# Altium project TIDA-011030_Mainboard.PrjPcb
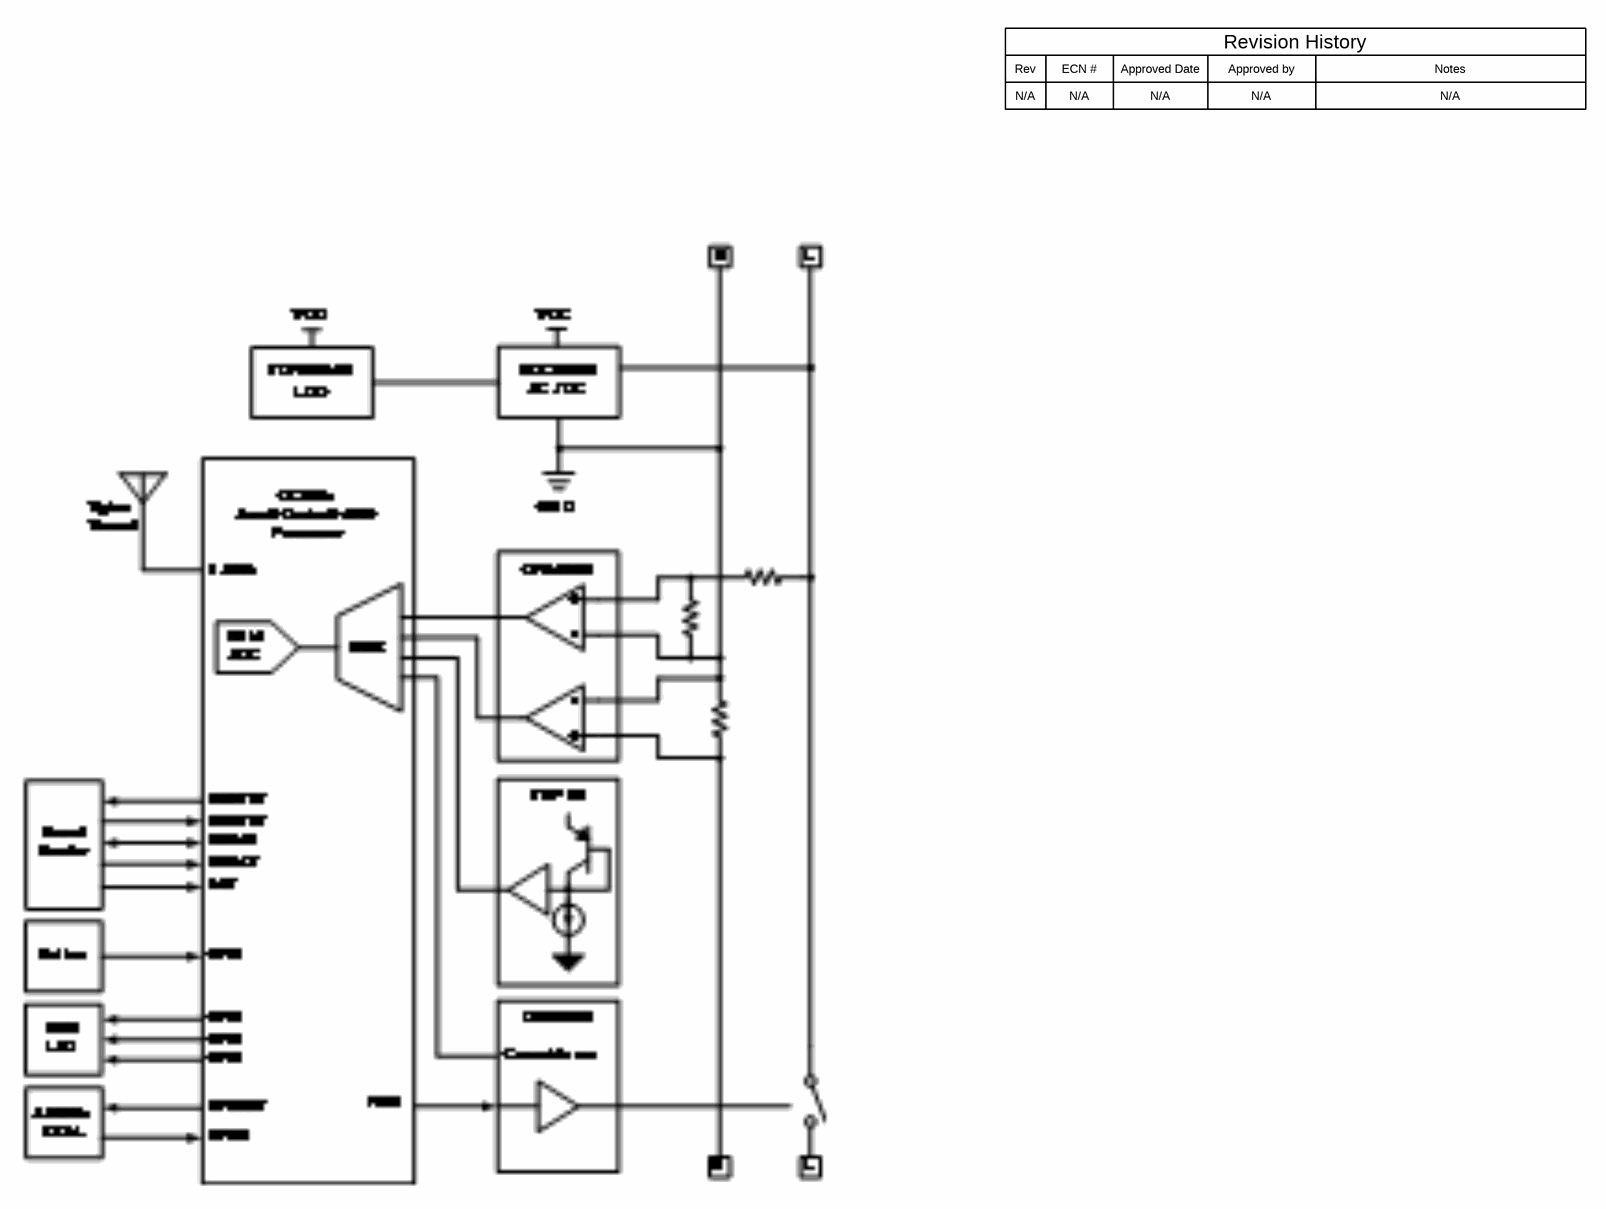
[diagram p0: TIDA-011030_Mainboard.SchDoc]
CopyrightYear: 2026; PCB_Layout: Simon Bozowicki; PCB_Rev: E1; PRJ_Customer: Public Release; PRJ_Engineer: Simon Bozowicki; PRJ_Number: TIDA-011030; PRJ_Title: Smart Circuit Breaker; SCH_Rev: E1; TechSupport: http://www.ti.com/support; TID: TIDA-011030
6 sheets, 114 parts. Net scope: flat (ports and power ports of the same name join across sheets).
Board file: TIDA-011030_Mainboard.PcbDoc
Sheets:
  TIDA-011030_Mainboard.SchDoc
  TIDA-011030_Mainboard_MCU.SchDoc
  TIDA-011030_Mainboard_Metering.SchDoc
  TIDA-011030_Mainboard_RelayDRV.SchDoc
  TIDA-011030_Mainboard_Power.SchDoc
  TIDA-011030_Mainboard_Hardware.SchDoc

## Sheet TIDA-011030_Mainboard.SchDoc: Block Diagram
size 431 x 279 mm; Date: Not shown in title block; ApprovedBy: Not shown in title block; CheckedBy: Not shown in title block; Author: Not shown in title block; CompanyName: Not shown in title block; Engineer: Not shown in title block; Organization: Not shown in title block; Address1: Not shown in title block; Address2: Not shown in title block; Address3: Not shown in title block; Address4: Not shown in title block; DocumentNumber: 1; Revision: Use project parameter SCH_Rev; SheetNumber: 1; SheetTotal: 6; PageSetup: Record=PageOptions¦CenterHorizontal=True¦CenterVertical=True¦PrintScale=1.00¦XCorrection=1.00¦YCorrection=1.00¦PrintKind=0¦BorderSize=5000000¦LeftOffset=0¦BottomOffset=0¦Orientation=2¦PaperLength=1000¦PaperWidth=1000¦Scale=100¦PaperSource=15¦PrintQuality=600¦MediaType=1¦DitherType=10¦PaperKind=Letter¦PrintScaleMode=1

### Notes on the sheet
- Rev
- N/A
- ECN #
- Approved Date
- Approved by
- Revision History
- Notes

## Sheet TIDA-011030_Mainboard_MCU.SchDoc: MCU
size 431 x 279 mm; Date: Not shown in title block; ApprovedBy: Not shown in title block; CheckedBy: Not shown in title block; Author: Not shown in title block; CompanyName: Not shown in title block; Engineer: Not shown in title block; Organization: Not shown in title block; Address1: Not shown in title block; Address2: Not shown in title block; Address3: Not shown in title block; Address4: Not shown in title block; DocumentNumber: 1; Revision: Use project parameter SCH_Rev; SheetNumber: 2; SheetTotal: 6; PageSetup: Record=PageOptions¦CenterHorizontal=True¦CenterVertical=True¦PrintScale=1.00¦XCorrection=1.00¦YCorrection=1.00¦PrintKind=0¦BorderSize=5000000¦LeftOffset=0¦BottomOffset=0¦Orientation=2¦PaperLength=1000¦PaperWidth=1000¦Scale=100¦PaperSource=15¦PrintQuality=600¦MediaType=1¦DitherType=10¦PaperKind=Letter¦PrintScaleMode=1
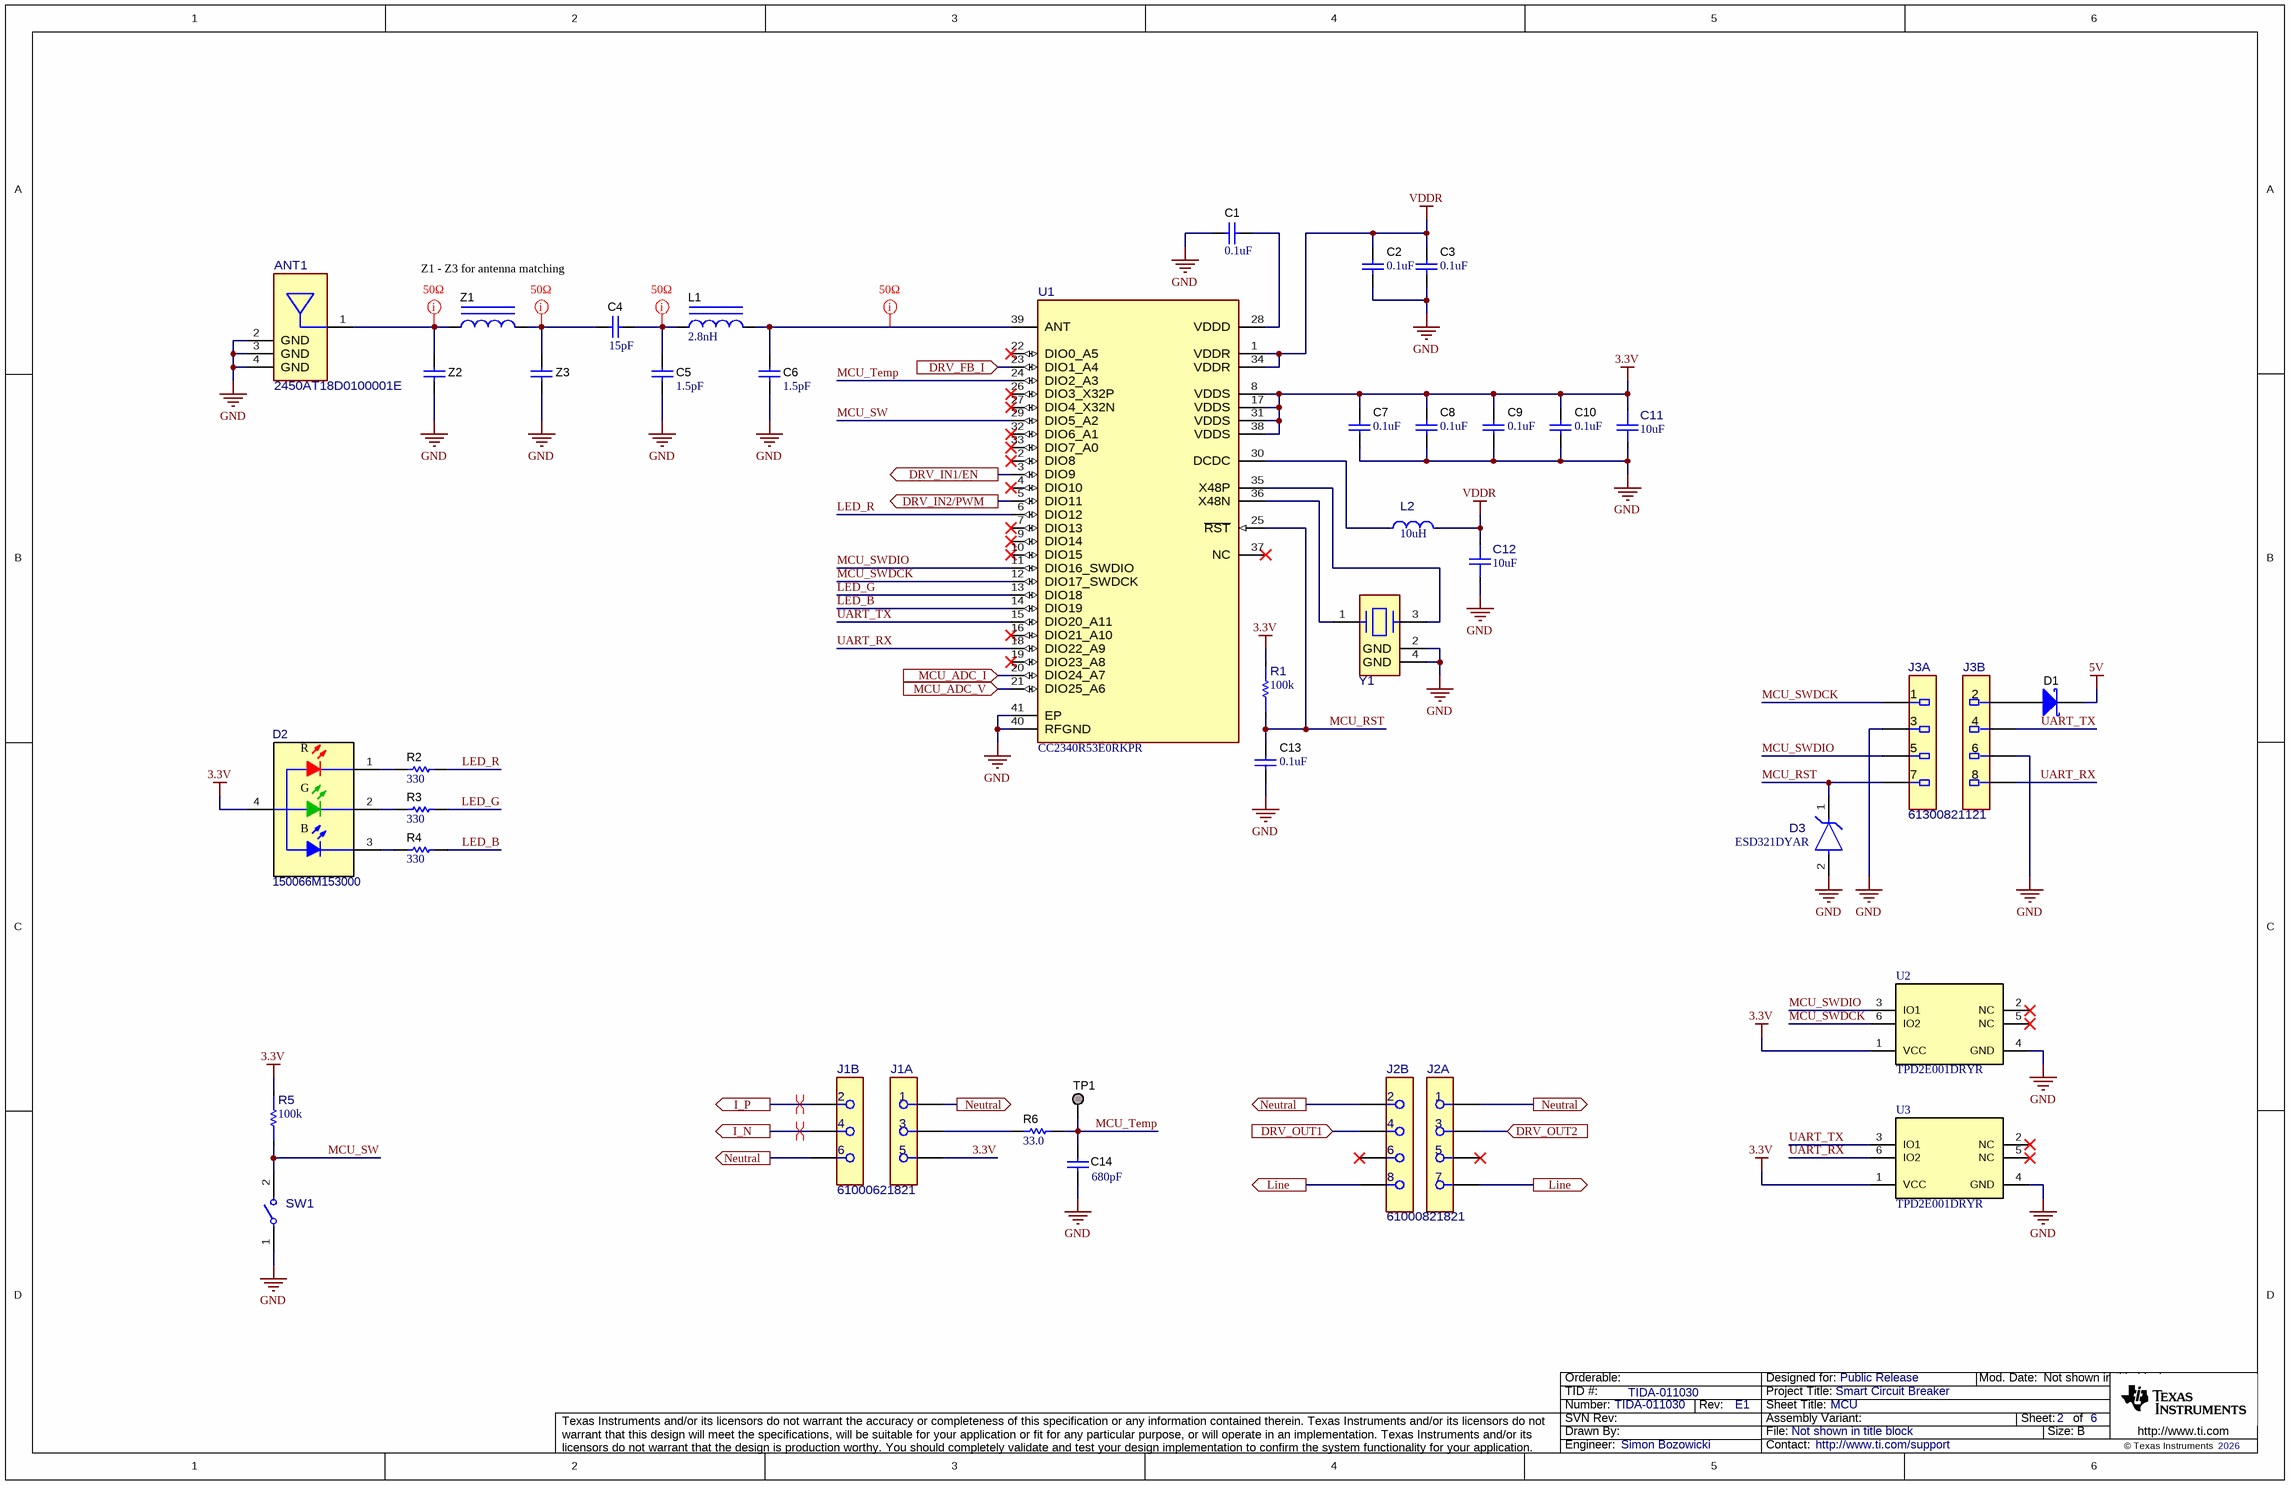
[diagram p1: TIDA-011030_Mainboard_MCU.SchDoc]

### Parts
ANT1  2450AT18D0100001E  [FP-2450AT18D0100001E_1206-MFG]
C1  ValueDisplayed: 0.1uF  [0402]  (hidden comment: GCM155R71C104KA55D)
C2  ValueDisplayed: 0.1uF  [0402]  (hidden comment: GCM155R71C104KA55D)
C3  ValueDisplayed: 0.1uF  [0402]  (hidden comment: GCM155R71C104KA55D)
C4  ValueDisplayed: 15pF  [0402]  (hidden comment: 04025A150FAT2A)
C5  ValueDisplayed: 1.5pF  [0402]  (hidden comment: GRM1555C1H1R5CA01D)
C6  ValueDisplayed: 1.5pF  [0402]  (hidden comment: GRM1555C1H1R5CA01D)
C7  ValueDisplayed: 0.1uF  [0402]  (hidden comment: GCM155R71C104KA55D)
C8  ValueDisplayed: 0.1uF  [0402]  (hidden comment: GCM155R71C104KA55D)
C9  ValueDisplayed: 0.1uF  [0402]  (hidden comment: GCM155R71C104KA55D)
C10  ValueDisplayed: 0.1uF  [0402]  (hidden comment: GCM155R71C104KA55D)
C11  ValueDisplayed: 10uF  [FP-GRT188D71A106ME13D_0603-MFG]  (hidden comment: GRT188D71A106ME13D)
C12  ValueDisplayed: 10uF  [FP-GRT188D71A106ME13D_0603-MFG]  (hidden comment: GRT188D71A106ME13D)
C13  ValueDisplayed: 0.1uF  [0402]  (hidden comment: GCM155R71C104KA55D)
C14  ValueDisplayed: 680pF  [0402]  (hidden comment: GRM155R71H681KA01D)
D1  PMEG3005ELS-QYL  [FP-PMEG3005ELS-QYL_DFN1006BD-2-0]  (value not drawn)
D2  150066M153000  [WL-SFCD0606_RGB]
D3  ESD321DYAR  [DYA0002A-MFG]
J1  61000621821  [FP-61000621821_HDR6-MFG]  (parts A,B of 2)
J2  61000821821  [FP-61000821821_CONN_RCPT_8-MFG]  (parts A,B of 2)
J3  61300821121  [FP-61300821121_HDR8-MFG]  (parts A,B of 2)
L1  ValueDisplayed: 2.8nH  [LQG15WZ_02]  (hidden comment: LQG15WZ2N8B02D)
L2  value 10uH  [FP-LQM18DH100M70L_0603-MFG]  (hidden comment: LQM18DH100M70L)
R1  value 100k  [FP-CRCW0402100KFKEDC_0402-MFG]  (hidden comment: CRCW0402100KFKEDC)
R2  ValueDisplayed: 330  [0402]  (hidden comment: ERJ-2RKF3300X)
R3  ValueDisplayed: 330  [0402]  (hidden comment: ERJ-2RKF3300X)
R4  ValueDisplayed: 330  [0402]  (hidden comment: ERJ-2RKF3300X)
R5  value 100k  [FP-CRCW0402100KFKEDC_0402-MFG]  (hidden comment: CRCW0402100KFKEDC)
R6  ValueDisplayed: 33.0  [0402]  (hidden comment: RC0402FR-0733RL)
SW1  430133050816  [FP-430133050816_SMD2-MFG]  (value not drawn)
TP1  TP_SM_1MM  [TP_SM_1MM]  (value not drawn)  (no BOM)
U1  CC2340R53E0RKPR  [RKP0040B-MFG]
U2  TPD2E001DRYR  [DRY0006A]
U3  TPD2E001DRYR  [DRY0006A]
Y1  TZ3908AAAO43  [FP-TZ3908AAAO43_SMT4_2MM05_1MM65-MFG]  (value not drawn)
Z1  LQG15WZ1N9S02D  [LQG15WZ_02]  (value not drawn)
Z2  GRM1555C1H1R5CA01D  [0402]  (value not drawn)
Z3  GRM1555C1H1R5CA01D  [0402]  (value not drawn)

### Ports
DRV_FB_I (in), DRV_IN1/EN (out), DRV_IN2/PWM (out), DRV_OUT1 (in), DRV_OUT2 (in), I_N (out), I_P (out), Line (out), MCU_ADC_I (in), MCU_ADC_V (in), Neutral (out)

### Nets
3.3V: C7.1 C8.1 C9.1 C10.1 C11.1 D2.4(A) J1.5 R1.2 R5.2 U1.8(VDDS) U1.17(VDDS) U1.31(VDDS) U1.38(VDDS) U2.1(VCC) U3.1(VCC)
5V: D1.1(K)
GND: ANT1.2(GND) ANT1.3(GND) ANT1.4(GND) C1.1 C2.2 C3.2 C5.2 C6.2 C7.2 C8.2 C9.2 C10.2 C11.2 C12.2 C13.2 C14.2 D3.2(GND) J1.1 J1.6 J2.1 J2.2 J3.3 J3.6 SW1.1 U1.40(RFGND) U1.41(EP) U2.4(GND) U3.4(GND) Y1.2(GND) Y1.4(GND) Z2.2 Z3.2 ; port Neutral
VDDR: C2.1 C3.1 C12.1 L2.2 U1.1(VDDR) U1.34(VDDR)
DRV_FB_I: U1.23(DIO1_A4) ; port DRV_FB_I
DRV_IN1/EN: U1.3(DIO9) ; port DRV_IN1/EN
DRV_IN2/PWM: U1.5(DIO11) ; port DRV_IN2/PWM
DRV_OUT1: J2.4 ; port DRV_OUT1
DRV_OUT2: J2.3 ; port DRV_OUT2
I_N: J1.4 ; port I_N
I_P: J1.2 ; port I_P
LED_B: R4.2 U1.14(DIO19)
LED_G: R3.2 U1.13(DIO18)
LED_R: R2.2 U1.6(DIO12)
Line: J2.7 J2.8 ; port Line
MCU_ADC_I: U1.20(DIO24_A7) ; port MCU_ADC_I
MCU_ADC_V: U1.21(DIO25_A6) ; port MCU_ADC_V
MCU_RST: C13.1 D3.1(IO) J3.7 R1.1 U1.25(~{RST})
MCU_SW: R5.1 SW1.2 U1.29(DIO5_A2)
MCU_SWDCK: J3.1 U1.12(DIO17_SWDCK) U2.6(IO2)
MCU_SWDIO: J3.5 U1.11(DIO16_SWDIO) U2.3(IO1)
MCU_Temp: C14.1 R6.2 TP1.1 U1.24(DIO2_A3)
UART_RX: J3.8 U1.18(DIO22_A9) U3.6(IO2)
UART_TX: J3.4 U1.15(DIO20_A11) U3.3(IO1)
NetANT1_1: ANT1.1(FEED) Z1.1 Z2.1
NetC1_2: C1.2 U1.28(VDDD)
NetC4_1: C4.1 C5.1 L1.1
NetC4_2: C4.2 Z1.2 Z3.1
NetC6_1: C6.1 L1.2 U1.39(ANT)
NetD1_2: D1.2(A) J3.2
NetD2_1: D2.1(K) R2.1
NetD2_2: D2.2(K) R3.1
NetD2_3: D2.3(K) R4.1
NetJ1_3: J1.3 R6.1
NetL2_1: L2.1 U1.30(DCDC)
NetU1_35: U1.35(X48P) Y1.3(2_IN/OUT)
NetU1_36: U1.36(X48N) Y1.1(1_IN/OUT)

Not connected (* = marked no-connect by the designer): J2 5* 6*; U1 2(DIO8)* 4(DIO10)* 7(DIO13)* 9(DIO14)* 10(DIO15)* 16(DIO21_A10)* 19(DIO23_A8)* 22(DIO0_A5)* 26(DIO3_X32P)* 27(DIO4_X32N)* 32(DIO6_A1)* 33(DIO7_A0)* 37(NC)*; U2 2(NC)* 5(NC)*; U3 2(NC)* 5(NC)*

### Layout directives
mark named 50Ω: NetANT1_1, NetC4_1, NetC4_2, NetC6_1
differential pair: I_N, I_P

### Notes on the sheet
- Z1 - Z3 for antenna matching

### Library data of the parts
ANT1 = CMP-0121196-1: 2.4GHz Chip RF Antenna 2.4GHz ~ 2.5GHz 1.5dBi Solder Surface Mount; Manufacturer: Johanson; SizeZ_mm: 1.3mm; AEC Qualified: No; Bandwidth: 0.1GHz; Gain: -1dB; Impedance: 50Ω; Number Of Bands: 1; Power_W: 3W; Return Loss: 10dB
C1-C3 C7-C10 C13 = CMP-0006351-2: CAP, CERM, 0.1 uF, 16 V, +/- 10%, X7R, 0402; Manufacturer: MuRata; TaMin_C: -55°C; Polarized: N; SizeAreaWB_mm2: 3; Value1: Unknown; U/M: EA; Value: 0.1uF; TaMax_C: 125°C; SizeZ_mm: 0.6; SizeX_mm: 1; SizeY_mm: 0.5; Value2: 16V; Cap_F: 100nF; AEC Category: Q200
C4 = CMP-0078217-1: CAP, CERM, 15 pF, 50 V,+/- 1%, C0G/NP0, 0402; Manufacturer: AVX; TaMin_C: -55°C; Polarized: N; Green_Lifecycle: Not Set; SizeAreaWB_mm2: 3; Green_REACh: Incomplete; U/M: EA; Value: 15pF; TaMax_C: 125°C; SizeZ_mm: 0.6; SizeX_mm: 1; SizeY_mm: 0.5; Value2: 50V; AEC Category: Q200
C5 C6 Z2 Z3 = CMP-0006433-2: CAP, CERM, 1.5 pF, 50 V, +/- 5%, C0G/NP0, 0402; Manufacturer: MuRata; TaMin_C: -55°C; Polarized: N; SizeAreaWB_mm2: 3; Value1: Unknown; U/M: EA; Value: 1.5pF; TaMax_C: 125°C; SizeZ_mm: 0.6; SizeX_mm: 1; SizeY_mm: 0.5; Value2: 50V; AEC Category: Q200
C11 C12 = CMP-0124993-1: Multi-Layer Ceramic Capacitor 10uF 10V X7T ±20% 0603 Paper T/R; Manufacturer: Murata; AEC Grade: Grade 1; AEC Qualified: Yes; Cap_F: 10µF; SizeZ_mm: 1mm; TempCo: +22/-33%; Value: 10µF
C14 = CMP-0006695-2: CAP, CERM, 680 pF, 50 V, +/- 10%, X7R, 0402; Manufacturer: MuRata; TaMin_C: -55°C; Polarized: N; SizeAreaWB_mm2: 3; Value1: Unknown; U/M: EA; Value: 680pF; TaMax_C: 125°C; SizeZ_mm: 0.6; SizeX_mm: 1; SizeY_mm: 0.5; Value2: 50V; AEC Category: Q200
D1 = CMP-0123792-2: Diode 30 V 500mA Surface Mount DFN1006BD-2; Manufacturer: Nexperia; AEC Qualified: Yes; SizeZ_mm: 0.5mm; TJmax_C: 150°C; Vr_V: 30V; AEC Grade: Grade 0; Cap_F: 24pF; Forward Current: 0.5A; Max Surge Forward Current: 3A; Peak Reverse Current: 70uA; TaMax_C: +150°C; TaMin_C: -55°C; AEC Category: Q101
D2 = CMP-0067667-2: LED, RGB, SMD; Manufacturer: Wurth Elektronik; Angle: 120.0; Io_A: 20mA; Value1: 0.078W; Vf_V: 3.3V; SizeZ_mm: 0.5; Tjmax_C: 85°C; SizeY_mm: 1.6; Power_TotalModule: 78mW; SizeAreaWB_mm2: 6.76; SizeArea_mm2: 2.56; Ir_A: 100µA; Type: InGaN; Vr_V: 5V
D3 = CMP-0125991-1: 0.9pF 3.6V ±30kV ESD protection diode with 6.8V 16A TLP clamping for USB 2.0 2-SOT-5X3 -55 to 150; Manufacturer: Texas Instruments; AEC Qualified: No; SizeZ_mm: 0.77mm; Ipp: 6A; Ppk: 40W; Breakdown Voltage: 4.5V; Clamping Voltage: 6.3V; Direction: Unidirectional; Number Of Channels: 1; Standoff Height: 0mm; TaMax_C: +125°C; TaMin_C: -40°C
J1 = CMP-0128753-1: WR-PHD 2.54 mm Dual Row SMT Socket Header 6 pins; Manufacturer: Wurth Electronics; ContactFinish: Gold; Current_A: 3A; Row_Count: 2; Voltage_V: 250V; AEC Qualified: No; Conn Gender: Female; Conn Orientation: Straight; DUT-Pitch_mm: 2.54mm; Is Female: yes; SizeZ_mm: 7.6mm; System: Connector
J2 = CMP-0128754-1: CONNECTOR, RCPT, 8POS, 2ROW, 2.54MM; Manufacturer: Wurth Electronics; ContactFinish: Gold; Current_A: 3A; Row_Count: 2; Voltage_V: 250V; AEC Qualified: No; Conn Gender: Female; Conn Orientation: Straight; Is Female: yes; SizeZ_mm: 7.6mm
J3 = CMP-0087153-1: CONN HEADER VERT 8POS 2.54MM; Manufacturer: Wurth Electronics; Voltage_V: 250V; Row_Count: 2; Current_A: 3A; ContactFinish: Gold
L1 = CMP-0080227-3: Inductor, Multilayer, Air Core, 2.8 nH, 0.9 A, 0.08 ohm, AEC-Q200 Grade 1, SMD; Manufacturer: MuRata; Irms: 0.9A @ 25C rise; SizeAreaWB_mm2: 3.2; DCR_ohm: 0.08; Value: 2.8nH; Imax_A: 900mA; SizeZ_mm: 0.6; SizeX_mm: 1; Value2: 0.9A; AEC Qualified: Y; AEC Category: Q200
L2 = CMP-0050143-1: 10 µH Shielded Multilayer Inductor 300 mA 1.37Ohm Max 0603 (1608 Metric); Manufacturer: Murata; AEC Grade: Grade 0; AEC Qualified: Yes; DCR_ohm: 1.37; Ind_H: 10µH; Irms: 300mA; Isat: 100mA; Material: Ferrite; SizeZ_mm: 0.95mm; Self Resonant Frequency: 32MHz; Shrouded: true; Test Frequency: 1MHz; Tolerance_%: 20%
R1 R5 = CMP-0092204-1: 100 kOhms ±1% 0.063W, 1/16W Chip Resistor 0402 (1005 Metric)  Thick Film; Manufacturer: Vishay; Power_W: 63mW; AEC Qualified: No; TempCo: 100ppm/°C; SizeZ_mm: 0.35mm; VDC_V: 50V
R2-R4 = CMP-0026694-1: RES, 330, 1%, 0.1 W, AEC-Q200 Grade 0, 0402; Manufacturer: Panasonic; Power_W: 100mW; TempCo: 100 ppm/C; Value_Code: 330R; U/M: EA; Value: 330; SizeX_mm: 1; SizeY_mm: 0.5; SizeZ_mm: 0.6; Value2: 0.1W; AEC Qualified: Y; VDC_V: 50V; AEC Grade: 0; AEC Category: Q200
R6 = CMP-0026732-1: RES, 33.0, 1%, 0.062 W, 0402; Manufacturer: Yageo America; Power_W: 62mW; TempCo: 100 ppm/C; Value_Code: 33R0; U/M: EA; Value: 33.0; Res_ohm: 33; SizeX_mm: 1; SizeY_mm: 0.5; SizeZ_mm: 0.6; Value2: 0.062W; AEC Qualified: N; VDC_V: 50V; AEC Category: Q200
SW1 = CMP-0128770-1: Tactile Switch SPST-NO Top Actuated Surface Mount; Manufacturer: Wurth; SizeZ_mm: 5.2mm; VDC_V: 16V; AEC Qualified: No; Coil Resistance_ohm: 100mΩ; Contact Current Rating: 50mA; Electromechanical Life: 100000Cycles; Operating Force: 160gf
TP1 = CMP-0003825-1: 1mm Test Point, SMT; Manufacturer: Any
U1 = CMP-0121694-1: SimpleLink™ Bluetooth ® 5.3 Low Energy Wireless MCU, VQFN40; Manufacturer: Texas Instruments; SizeZ_mm: 1mm; AEC Qualified: No; AEC Grade: NA; Core Architecture: ARM Cortex-M0+; Data Bus Width: 32bits; Frequency_Fixed: 48MHz; Interface: I2C,SPI,UART; Max Supply Voltage: 3.8V; Memory Size: 512KBytes; Memory Type: FLASH; Min Supply Voltage: 1.71V; Number Of A/D Converters: 1; Number Of Adc Channels: 8; Number Of I/Os: 26; Number Of Timers/Counters: 4; Ram Size: 36KBytes; Standoff Height: 0mm; TaMax_C: +125°C; TaMin_C: -40°C
U2 U3 = CMP-0043099-3: Low-Capacitance 2-Channel +/-15kV ESD Protection Array for High-Speed Data Interfaces, DRY0006A (USON-6); Manufacturer: Texas Instruments; IO Leakage Current(nA): 1; IEC 61000-4-2 Air-Gap(+/- kV): 15; USB High Speed: TRUE; IO Capacitance(Typ)(pF): 1.5; Eco-Plan: Green (RoHS & no Sb/Br); Breakdown Voltage(Min)(V): 11; IEC 61000-4-2 Contact(+/- kV): 8; AEC Category: Q200; AEC Qualified: N; CompType: IC; SizeAreaWB_mm2: 4.9; SizeArea_mm2: 1.45; SizeX_mm: 1.0; SizeZ_mm: 0.6; Rating: Catalog
Y1 = CMP-0001392-1: Crystal Unit SMD 2.0x1.6 48.0MHz; Manufacturer: TAI-SAW Thechnology; Frequency Stability: 30ppm; Frequency_Fixed: 48MHz; SizeZ_mm: 0.5mm; AEC Qualified: No; Frequency Tolerance: 5ppm; Load Capacitance: 7pF; Esr: 30
Z1 = CMP-0080187-3: Inductor, Multilayer, Air Core, 1.9 nH, 1 A, 0.05 ohm, AEC-Q200 Grade 1, SMD; Manufacturer: MuRata; Irms: 1A @ 25C rise; SizeAreaWB_mm2: 3.2; DCR_ohm: 0.05; Value: 1.9nH; Imax_A: 1A; SizeZ_mm: 0.6; SizeX_mm: 1; AEC Qualified: Y; AEC Category: Q200

## Sheet TIDA-011030_Mainboard_Metering.SchDoc: Metering
size 431 x 279 mm; Date: Not shown in title block; ApprovedBy: Not shown in title block; CheckedBy: Not shown in title block; Author: Not shown in title block; CompanyName: Not shown in title block; Engineer: Not shown in title block; Organization: Not shown in title block; Address1: Not shown in title block; Address2: Not shown in title block; Address3: Not shown in title block; Address4: Not shown in title block; DocumentNumber: 1; Revision: Use project parameter SCH_Rev; SheetNumber: 3; SheetTotal: 6; PageSetup: Record=PageOptions¦CenterHorizontal=True¦CenterVertical=True¦PrintScale=1.00¦XCorrection=1.00¦YCorrection=1.00¦PrintKind=0¦BorderSize=5000000¦LeftOffset=0¦BottomOffset=0¦Orientation=2¦PaperLength=1000¦PaperWidth=1000¦Scale=100¦PaperSource=15¦PrintQuality=600¦MediaType=1¦DitherType=10¦PaperKind=Letter¦PrintScaleMode=1
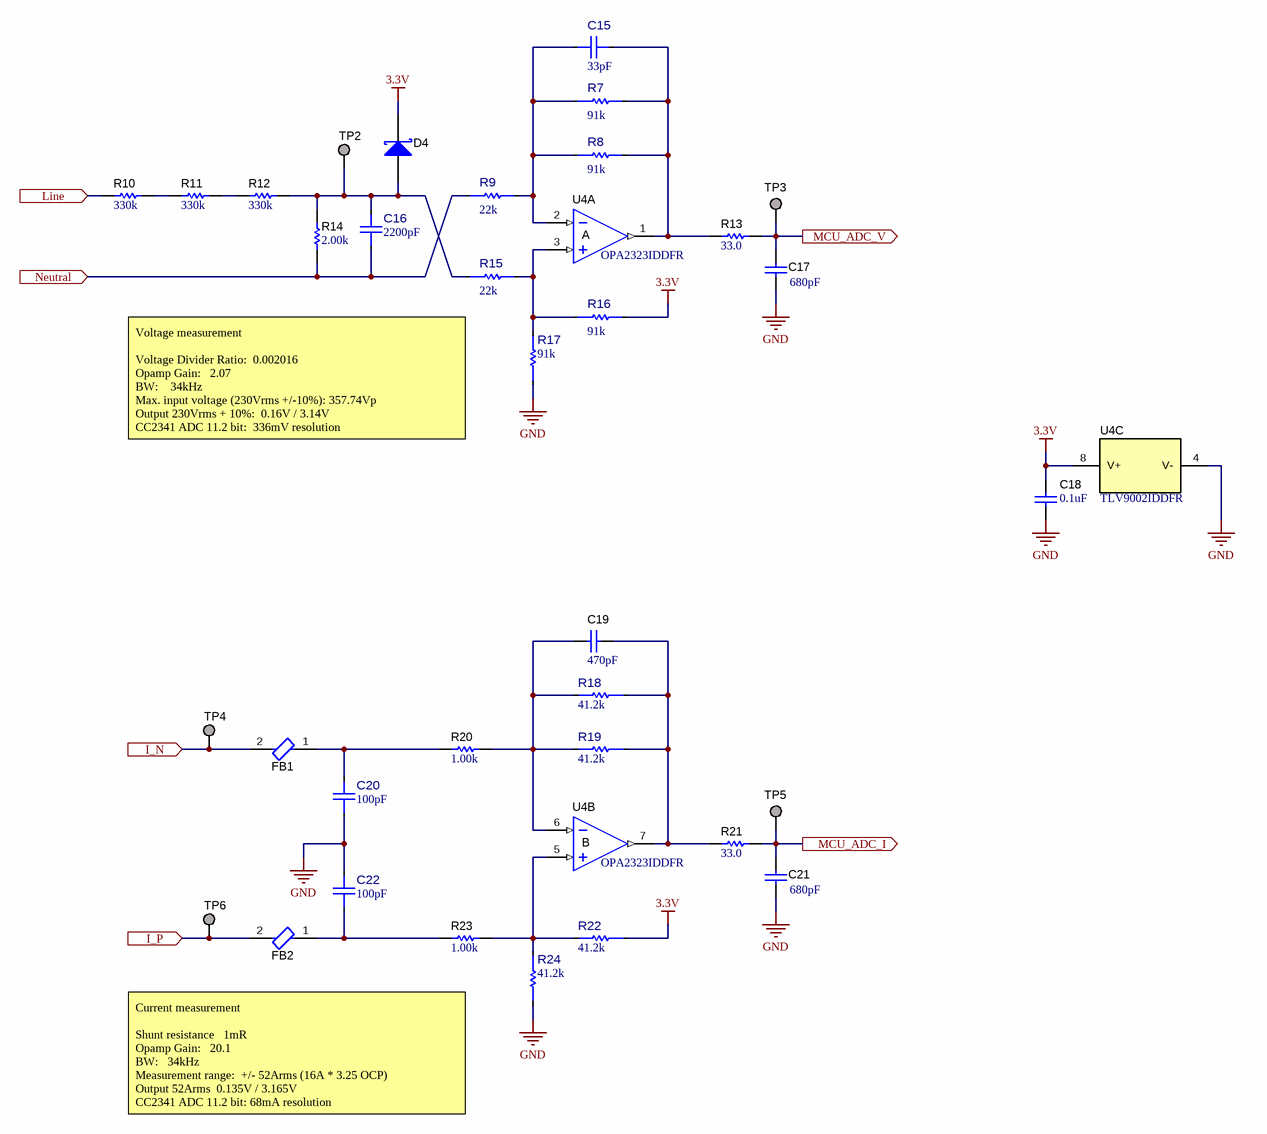
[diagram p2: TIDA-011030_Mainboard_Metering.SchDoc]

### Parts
C15  ValueDisplayed: 33pF  [FP-885012005058_0402-MFG]  (hidden comment: 885012005058)
C16  ValueDisplayed: 2200pF  [FP-C0402C222F3GAC7867_0402-MFG]  (hidden comment: C0402C222F3GAC7867)
C17  ValueDisplayed: 680pF  [0402]  (hidden comment: GRM155R71H681KA01D)
C18  ValueDisplayed: 0.1uF  [0402]  (hidden comment: GCM155R71C104KA55D)
C19  ValueDisplayed: 470pF  [0402]  (hidden comment: GRM1555C1H471JA01D)
C20  ValueDisplayed: 100pF  [FP-04025A101JAT2A_0402-MFG]  (hidden comment: 04025A101JAT2A)
C21  ValueDisplayed: 680pF  [0402]  (hidden comment: GRM155R71H681KA01D)
C22  ValueDisplayed: 100pF  [FP-04025A101JAT2A_0402-MFG]  (hidden comment: 04025A101JAT2A)
D4  PMEG3005ELS-QYL  [FP-PMEG3005ELS-QYL_DFN1006BD-2-0]  (value not drawn)
FB1  74269244182  [FP-74269244182_0402-MFG]  (value not drawn)
FB2  74269244182  [FP-74269244182_0402-MFG]  (value not drawn)
R7  value 91k  [FP-ERA-2AEB913X_0402-MFG]  (hidden comment: ERA-2AEB913X)
R8  value 91k  [FP-ERA-2AEB913X_0402-MFG]  (hidden comment: ERA-2AEB913X)
R9  value 22k  [FP-ERA2AEB223X_0402-MFG]  (hidden comment: ERA2AEB223X)
R10  ValueDisplayed: 330k  [TNPV1206]  (hidden comment: TNPV1206330KBEEN)
R11  ValueDisplayed: 330k  [TNPV1206]  (hidden comment: TNPV1206330KBEEN)
R12  ValueDisplayed: 330k  [TNPV1206]  (hidden comment: TNPV1206330KBEEN)
R13  ValueDisplayed: 33.0  [0402]  (hidden comment: RC0402FR-0733RL)
R14  ValueDisplayed: 2.00k  [0603]  (hidden comment: RT0603BRD072KL)
R15  value 22k  [FP-ERA2AEB223X_0402-MFG]  (hidden comment: ERA2AEB223X)
R16  value 91k  [FP-ERA-2AEB913X_0402-MFG]  (hidden comment: ERA-2AEB913X)
R17  value 91k  [FP-ERA-2AEB913X_0402-MFG]  (hidden comment: ERA-2AEB913X)
R18  value 41.2k  [FP-RT0402BRD0741K2L_0402-MFG]  (hidden comment: RT0402BRD0741K2L)
R19  value 41.2k  [FP-RT0402BRD0741K2L_0402-MFG]  (hidden comment: RT0402BRD0741K2L)
R20  ValueDisplayed: 1.00k  [0402]  (hidden comment: ERA-2AEB102X)
R21  ValueDisplayed: 33.0  [0402]  (hidden comment: RC0402FR-0733RL)
R22  value 41.2k  [FP-RT0402BRD0741K2L_0402-MFG]  (hidden comment: RT0402BRD0741K2L)
R23  ValueDisplayed: 1.00k  [0402]  (hidden comment: ERA-2AEB102X)
R24  value 41.2k  [FP-RT0402BRD0741K2L_0402-MFG]  (hidden comment: RT0402BRD0741K2L)
TP2  TP_SM_1MM  [TP_SM_1MM]  (value not drawn)  (no BOM)
TP3  TP_SM_1MM  [TP_SM_1MM]  (value not drawn)  (no BOM)
TP4  TP_SM_1MM  [TP_SM_1MM]  (value not drawn)  (no BOM)
TP5  TP_SM_1MM  [TP_SM_1MM]  (value not drawn)  (no BOM)
TP6  TP_SM_1MM  [TP_SM_1MM]  (value not drawn)  (no BOM)
U4  PartNumber: OPA2323IDDFR  [DDF0008A_N]  (hidden comment: TLV9002IDDFR)  (parts A,B,C of 3)

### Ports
I_N (in), I_P (in), Line (in), MCU_ADC_I (out), MCU_ADC_V (out), Neutral (in)

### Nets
3.3V: C18.1 D4.1(K) R16.2 R22.1 U4.8(V+)
GND: C16.1 C17.2 C18.2 C20.1 C21.2 C22.2 R9.1 R14.1 R17.1 R24.2 U4.4(V-) ; port Neutral
I_N: FB1.2 TP4.1 ; port I_N
I_P: FB2.2 TP6.1 ; port I_P
Line: R10.2 ; port Line
MCU_ADC_I: C21.1 R21.2 TP5.1 ; port MCU_ADC_I
MCU_ADC_V: C17.1 R13.2 TP3.1 ; port MCU_ADC_V
NetC15_1: C15.1 R7.1 R8.1 R9.2 U4.2(IN-)
NetC15_2: C15.2 R7.2 R8.2 R13.1 U4.1(OUT)
NetC16_2: C16.2 D4.2(A) R12.1 R14.2 R15.1 TP2.1
NetC19_1: C19.1 R18.1 R19.1 R21.1 U4.7(OUT)
NetC19_2: C19.2 R18.2 R19.2 R20.2 U4.6(IN-)
NetC20_2: C20.2 FB1.1 R20.1
NetC22_1: C22.1 FB2.1 R23.1
NetR10_1: R10.1 R11.2
NetR11_1: R11.1 R12.2
NetR15_2: R15.2 R16.1 R17.2 U4.3(IN+)
NetR22_2: R22.2 R23.2 R24.1 U4.5(IN+)

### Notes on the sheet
- (near R15) Voltage measurement
  Voltage Divider Ratio:		0.002016
  Opamp Gain:			2.07
  BW:				34kHz
  Max. input voltage (230Vrms +/-10%):	357.74Vp
  Output 230Vrms + 10%:		0.16V / 3.14V
  CC2341 ADC 11.2 bit:		336mV resolution
- Current measurement
  Shunt resistance 		1mR
  Opamp Gain: 		20.1
  BW:			34kHz
  Measurement range:		+/- 52Arms (16A * 3.25 OCP)
  Output 52Arms		0.135V / 3.165V
  CC2341 ADC 11.2 bit:	68mA resolution

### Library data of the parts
C15 = CMP-0097306-1: 33 pF ±5% 50V Ceramic Capacitor C0G, NP0 0402 (1005 Metric); Manufacturer: Wurth Electronics; AEC Qualified: No; Value: 33pF; TempCo: 30ppm/°C; SizeZ_mm: 0.55mm
C16 = CMP-0097646-1: 2200 pF ±1% 25V Ceramic Capacitor C0G, NP0 0402 (1005 Metric); Manufacturer: KEMET; TempCo: 30ppm/°C; Cap_F: 2.2nF; AEC Qualified: No; Value: 2.2nF; SizeZ_mm: 0.55mm
C17 C21 = CMP-0006695-2: as C14 on sheet TIDA-011030_Mainboard_MCU
C18 = CMP-0006351-2: as C1 on sheet TIDA-011030_Mainboard_MCU
C19 = CMP-0006470-2: CAP, CERM, 470 pF, 50 V, +/- 5%, C0G/NP0, 0402; Manufacturer: MuRata; TaMin_C: -55°C; Polarized: N; SizeAreaWB_mm2: 3; Value1: Unknown; U/M: EA; Value: 470pF; TaMax_C: 125°C; SizeZ_mm: 0.6; SizeX_mm: 1; SizeY_mm: 0.5; Value2: 50V; AEC Category: Q200
C20 C22 = CMP-0092080-1: 100pF ±5% 50V Ceramic Capacitor C0G, NP0 0402 (1005 Metric); Manufacturer: AVX; TempCo: 30ppm/°C; AEC Qualified: No; SizeZ_mm: 0.56mm
D4 = CMP-0123792-2: as D1 on sheet TIDA-011030_Mainboard_MCU
FB1 FB2 = CMP-0091663-1: 1.8 kOhms @ 100MHz 1 Power, Signal Line Ferrite Bead 0402 (1005 Metric) 210mA 2.1Ohm; Manufacturer: Wurth Electronics; SizeZ_mm: 0.55mm; AEC Qualified: No; DCR_ohm: 2.1; Tolerance_%: 25%; Test Frequency: 1GHz; Impedance At Frequency: 1800Ω @ 100MHz
R7 R8 R16 R17 = CMP-0128762-1: Res Thin Film 0402 91K Ohm 0.1% 0.063W ±25ppm/°C Molded SMD Punched Carrier T/R; Manufacturer: Panasonic; AEC Grade: Grade 0; AEC Qualified: Yes; Power_W: 63mW; SizeZ_mm: 0.4mm; VDC_V: 50V
R9 R15 = CMP-0121025-1: 22 kOhms ±0.1% 0.063W, 1/16W Chip Resistor 0402 (1005 Metric) Automotive AEC-Q200 Thin Film; Manufacturer: Panasonic; AEC Grade: Grade 1; AEC Qualified: Yes; Power_W: 63mW; SizeZ_mm: 0.4mm; TempCo: 25ppm/°C; VDC_V: 50V
R10-R12 = CMP-0018811-2: RES, 330 k, 0.1%, 1 W, 1206; Manufacturer: Vishay Draloric; Power_W: 1W; TempCo: 25 ppm/C; U/M: EA; Value: 330k; SizeX_mm: 3.2; SizeY_mm: 1.6; SizeZ_mm: 0.65; SizeArea_mm2: 5.12; AEC Qualified: N; VDC_V: 700V; AEC Category: Q200
R13 R21 = CMP-0026732-1: as R6 on sheet TIDA-011030_Mainboard_MCU
R14 = CMP-0024089-3: RES, 2.00 k, 0.1%, 0.1 W, 0603; Manufacturer: Yageo America; Power_W: 100mW; TempCo: 25 ppm/C; Value_Code: 2k00; U/M: EA; Value: 2.00k; EIA_Code: E192; Res_ohm: 2k; SizeX_mm: 1.6; SizeY_mm: 0.8; SizeZ_mm: 1; Value2: 0.1W; SizeArea_mm2: 1.28; VDC_V: 75V; AEC Category: Q200
R18 R19 R22 R24 = CMP-0092058-1: High Precision-High Stability Chip Resistor Thin Film 0402 41.2kOhm 0.1% Paper T/R; Manufacturer: Yageo; TempCo: 25ppm/°C; AEC Qualified: No; SizeZ_mm: 0.35mm; Power_W: 63mW; VDC_V: 50V
R20 R23 = CMP-0026770-1: RES, 1.00 k, 0.1%, 0.063 W, 0402; Manufacturer: Panasonic; Power_W: 63mW; TempCo: 25 ppm/C; Value_Code: 1k00; U/M: EA; Value: 1.00k; EIA_Code: E192; Res_ohm: 1k; SizeX_mm: 1; SizeY_mm: 0.5; SizeZ_mm: 0.6; Value2: 0.063W; VDC_V: 50V; AEC Category: Q200
TP2-TP6 = CMP-0003825-1: 1mm Test Point, SMT; Manufacturer: Any
U4 = CMP-0086102-1: TLV9002IDDFR, DDF0008A (SOT-23-THN-8); Manufacturer: Texas Instruments; SizeY_mm: 2.9; CompType: IC; SizeX_mm: 2.8; AEC Category: Q200; SizeAreaWB_mm2: 14.82; AEC Qualified: N; SizeArea_mm2: 8.12; SizeZ_mm: 1.1

## Sheet TIDA-011030_Mainboard_RelayDRV.SchDoc: Relay Driver
size 431 x 279 mm; Date: Not shown in title block; ApprovedBy: Not shown in title block; CheckedBy: Not shown in title block; Author: Not shown in title block; CompanyName: Not shown in title block; Engineer: Not shown in title block; Organization: Not shown in title block; Address1: Not shown in title block; Address2: Not shown in title block; Address3: Not shown in title block; Address4: Not shown in title block; DocumentNumber: 1; Revision: Use project parameter SCH_Rev; SheetNumber: 4; SheetTotal: 6; PageSetup: Record=PageOptions¦CenterHorizontal=True¦CenterVertical=True¦PrintScale=1.00¦XCorrection=1.00¦YCorrection=1.00¦PrintKind=0¦BorderSize=5000000¦LeftOffset=0¦BottomOffset=0¦Orientation=2¦PaperLength=1000¦PaperWidth=1000¦Scale=100¦PaperSource=15¦PrintQuality=600¦MediaType=1¦DitherType=10¦PaperKind=Letter¦PrintScaleMode=1
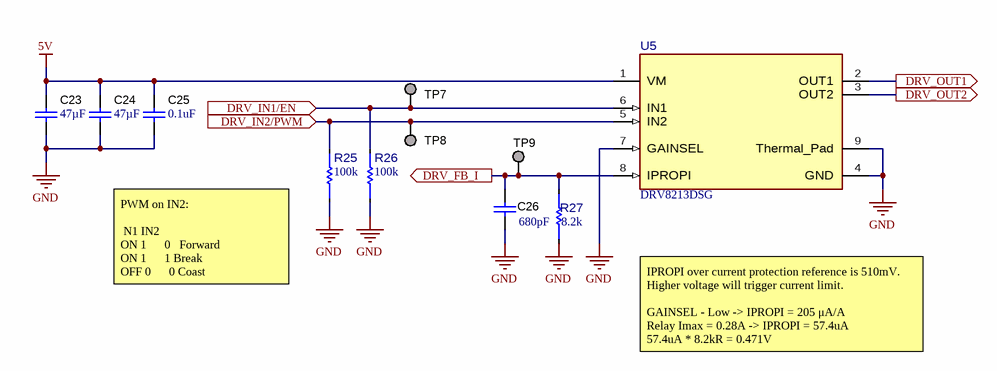
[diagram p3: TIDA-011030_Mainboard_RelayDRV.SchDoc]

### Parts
C23  ValueDisplayed: 47µF  [0805L]  (hidden comment: GRM21BR61A476ME15L)
C24  ValueDisplayed: 47µF  [0805L]  (hidden comment: GRM21BR61A476ME15L)
C25  ValueDisplayed: 0.1uF  [0402]  (hidden comment: GCM155R71C104KA55D)
C26  ValueDisplayed: 680pF  [0402]  (hidden comment: GRM155R71H681KA01D)
R25  value 100k  [FP-CRCW0402100KFKEDC_0402-MFG]  (hidden comment: CRCW0402100KFKEDC)
R26  value 100k  [FP-CRCW0402100KFKEDC_0402-MFG]  (hidden comment: CRCW0402100KFKEDC)
R27  value 8.2k  [FP-RC0402FR-078K2L_0402-MFG]  (hidden comment: RC0402FR-078K2L)
TP7  TP_SM_1MM  [TP_SM_1MM]  (value not drawn)  (no BOM)
TP8  TP_SM_1MM  [TP_SM_1MM]  (value not drawn)  (no BOM)
TP9  TP_SM_1MM  [TP_SM_1MM]  (value not drawn)  (no BOM)
U5  DRV8213DSG  [DSG0008A-MFG]

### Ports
DRV_FB_I (out), DRV_IN1/EN (in), DRV_IN2/PWM (in), DRV_OUT1 (out), DRV_OUT2 (out)

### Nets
5V: C23.1 C24.1 C25.1 U5.1(VM)
GND: C23.2 C24.2 C25.2 C26.2 R25.1 R26.1 R27.1 U5.4(GND) U5.7(GAINSEL) U5.9(Thermal_Pad)
DRV_FB_I: C26.1 R27.2 TP9.1 U5.8(IPROPI) ; port DRV_FB_I
DRV_IN1/EN: R26.2 TP7.1 U5.6(IN1) ; port DRV_IN1/EN
DRV_IN2/PWM: R25.2 TP8.1 U5.5(IN2) ; port DRV_IN2/PWM
DRV_OUT1: U5.2(OUT1) ; port DRV_OUT1
DRV_OUT2: U5.3(OUT2) ; port DRV_OUT2

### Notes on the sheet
- (near R25) PWM on IN2:
  N1 IN2
  ON	1      0  	Forward
  ON	1      1	Break
  OFF	0      0	Coast
- IPROPI over current protection reference is 510mV. Higher voltage will trigger current limit.
  GAINSEL - Low -> IPROPI = 205 μA/A
  Relay Imax = 0.28A -> IPROPI = 57.4uA
  57.4uA * 8.2kR = 0.471V

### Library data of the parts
C23 C24 = CMP-0078699-1: CAP, CERM, 47 µF, 10 V,+/- 20%, X5R, 0805; Manufacturer: MuRata; TaMin_C: -55°C; Polarized: N; Green_Lifecycle: Active; SizeAreaWB_mm2: 6.75; Green_REACh: Passed; U/M: EA; Value: 47uF; TaMax_C: 85°C; SizeZ_mm: 1.45; SizeX_mm: 2; SizeY_mm: 1.25; Cap_Case: 0805; Value2: 10V; SizeArea_mm2: 2.5; AEC Category: Q200
C25 = CMP-0006351-2: as C1 on sheet TIDA-011030_Mainboard_MCU
C26 = CMP-0006695-2: as C14 on sheet TIDA-011030_Mainboard_MCU
R25 R26 = CMP-0092204-1: as R1 on sheet TIDA-011030_Mainboard_MCU
R27 = CMP-0120311-1: Res Thick Film 0402 8.2K Ohm 1% 0.063W(1/16W) ±100ppm/°C Pad SMD T/R; Manufacturer: Yageo; AEC Qualified: No; Power_W: 63mW; SizeZ_mm: 0.4mm; VDC_V: 50V
TP7-TP9 = CMP-0003825-1: 1mm Test Point, SMT; Manufacturer: Any
U5 = CMP-0097135-1: 4-A Brushed DC Motor Driver with Integrated Current Sense, Current Regulation and Stall Detection; Manufacturer: Texas Instruments; Min Supply Voltage: 1.65V; Switching Frequency: 100kHz; Nominal Supply Current: 1.2mA; SizeZ_mm: 0.8mm; Standoff Height: 0mm; TJmax_C: +150°C; TaMax_C: +125°C; TaMin_C: -40°C; Max Supply Voltage: 11V; AEC Qualified: No; Number Of Outputs: 2

## Sheet TIDA-011030_Mainboard_Power.SchDoc: Power Supply
size 431 x 279 mm; Date: Not shown in title block; ApprovedBy: Not shown in title block; CheckedBy: Not shown in title block; Author: Not shown in title block; CompanyName: Not shown in title block; Engineer: Not shown in title block; Organization: Not shown in title block; Address1: Not shown in title block; Address2: Not shown in title block; Address3: Not shown in title block; Address4: Not shown in title block; DocumentNumber: 2; Revision: Use project parameter SCH_Rev; SheetNumber: 5; SheetTotal: 6; PageSetup: Record=PageOptions¦CenterHorizontal=True¦CenterVertical=True¦PrintScale=1.00¦XCorrection=1.00¦YCorrection=1.00¦PrintKind=0¦BorderSize=5000000¦LeftOffset=0¦BottomOffset=0¦Orientation=2¦PaperLength=1000¦PaperWidth=1000¦Scale=100¦PaperSource=15¦PrintQuality=600¦MediaType=1¦DitherType=10¦PaperKind=Letter¦PrintScaleMode=1
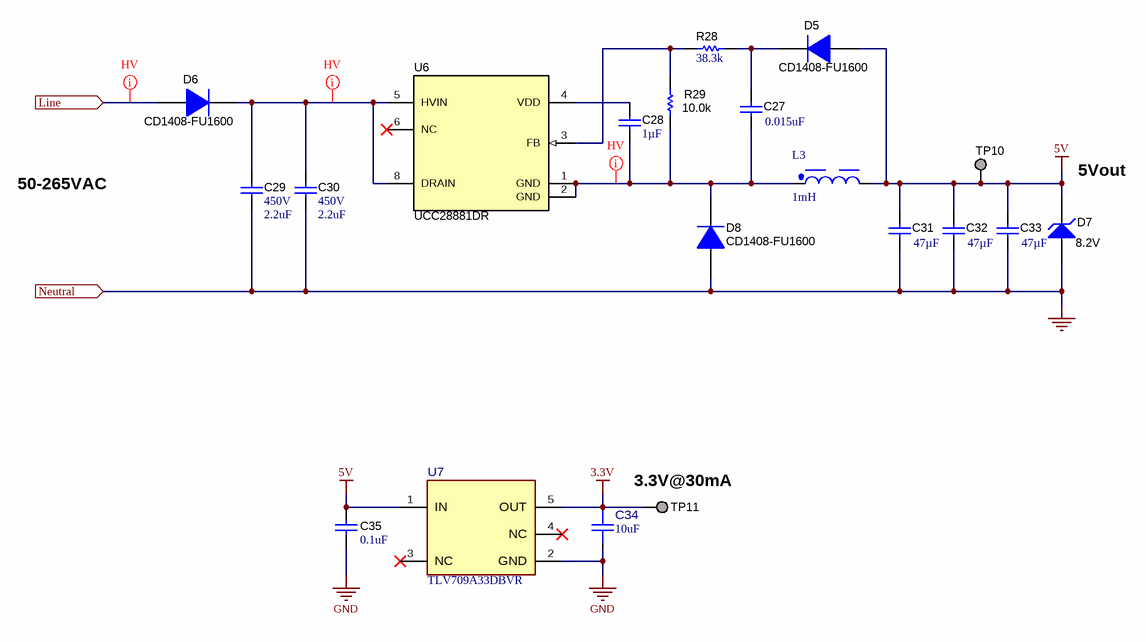
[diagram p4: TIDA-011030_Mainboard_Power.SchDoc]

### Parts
C27  ValueDisplayed: 0.015uF  [0402S]  (hidden comment: GRM155R71H153KA12D)
C28  ValueDisplayed: 1µF  [0402]  (hidden comment: GRM155R61C105MA12D)
C29  VDC_V: 450V  ValueDisplayed: 2.2uF  [2220_280]  (hidden comment: C5750X6S2W225K250KA)
C30  VDC_V: 450V  ValueDisplayed: 2.2uF  [2220_280]  (hidden comment: C5750X6S2W225K250KA)
C31  ValueDisplayed: 47µF  [0805L]  (hidden comment: GRM21BR61A476ME15L)
C32  ValueDisplayed: 47µF  [0805L]  (hidden comment: GRM21BR61A476ME15L)
C33  ValueDisplayed: 47µF  [0805L]  (hidden comment: GRM21BR61A476ME15L)
C34  ValueDisplayed: 10uF  [FP-GRT188D71A106ME13D_0603-MFG]  (hidden comment: GRT188D71A106ME13D)
C35  ValueDisplayed: 0.1uF  [0402]  (hidden comment: GCM155R71C104KA55D)
D5  CD1408-FU1600  [Diode_1408]
D6  CD1408-FU1600  [Diode_1408]
D7  value 8.2V  [SOD-123]  (hidden comment: DDZ8V2C-7)
D8  CD1408-FU1600  [Diode_1408]
L3  Inductance: 1mH  [WE-LQS_6045]  (hidden comment: 74404064102)
R28  ValueDisplayed: 38.3k  [0402S]  (hidden comment: CRCW040238K3FKED)
R29  ValueDisplayed: 10.0k  [0402S]  (hidden comment: ERJ-2RKF1002X)
TP10  TP_SM_1MM  [TP_SM_1MM]  (value not drawn)  (no BOM)
TP11  TP_SM_1MM  [TP_SM_1MM]  (value not drawn)  (no BOM)
U6  UCC28881DR  [D0007A_N]
U7  TLV709A33DBVR  [DBV0005A-MFG]

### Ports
Line (in), Neutral (in)

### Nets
3.3V: C34.1 TP11.1 U7.5(OUT)
5V: C31.1 C32.1 C33.1 C35.1 D5.2(A) D7.1(K) L3.2 TP10.1 U7.1(IN)
GND: C29.2 C30.2 C31.2 C32.2 C33.2 C34.2 C35.2 D7.2(A) D8.2(A) U7.2(GND) ; port Neutral
Line: D6.2(A) ; port Line
NetC27_1: C27.1 D5.1(K) R28.2
NetC27_2: C27.2 C28.2 D8.1(K) L3.1 R29.1 U6.1(GND) U6.2(GND)
NetC28_1: C28.1 U6.4(VDD)
NetC29_1: C29.1 C30.1 D6.1(K) U6.5(HVIN) U6.8(DRAIN)
NetR28_1: R28.1 R29.2 U6.3(FB)

Not connected (* = marked no-connect by the designer): U6 6(NC)*; U7 3(NC)* 4(NC)*

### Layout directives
net class HV: Line, NetC27_2, NetC29_1

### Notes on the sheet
- (near D7) 5Vout
- 50-265VAC
- (near TP11) 3.3V@30mA

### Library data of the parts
C27 = CMP-0006679-2: CAP, CERM, 0.015 uF, 50 V, +/- 10%, X7R, 0402; Manufacturer: MuRata; TaMin_C: -55°C; Polarized: N; SizeAreaWB_mm2: 3; Value1: Unknown; U/M: EA; TaMax_C: 125°C; SizeZ_mm: 0.6; SizeX_mm: 1; SizeY_mm: 0.5; Cap_Case: 0402; Value2: 50V; Cap_F: 15nF; AEC Category: Q200
C28 = CMP-0084375-1: CAP, CERM, 1 µF, 16 V,+/- 20%, X5R, 0402; Manufacturer: MuRata; SizeX_mm: 1; AEC Category: Q200; SizeAreaWB_mm2: 3; U/M: EA; Value2: 16V; TaMin_C: -55°C; AEC Qualified: N; SizeZ_mm: 0.6; TaMax_C: 85°C; SizeArea_mm2: 0.5; Value: 1uF
C29 C30 = CMP-0009372-2: CAP, CERM, 2.2 uF, 450 V, +/- 10%, X6S, 2220; Manufacturer: TDK; TaMin_C: -55°C; Polarized: N; SizeAreaWB_mm2: 53.9; Value1: Unknown; U/M: EA; Value: 2.2uF; TaMax_C: 105°C; SizeZ_mm: 2.8; SizeX_mm: 5.7; SizeY_mm: 5; Cap_Case: 2220; SizeArea_mm2: 28.5; Cap_F: 2.2µF; AEC Category: Q200
C31-C33 = CMP-0078699-1: as C23 on sheet TIDA-011030_Mainboard_RelayDRV
C34 = CMP-0124993-1: as C11 on sheet TIDA-011030_Mainboard_MCU
C35 = CMP-0006351-2: as C1 on sheet TIDA-011030_Mainboard_MCU
D5 D6 D8 = CMP-0029015-2: Diode, Ultrafast, 600 V, 1 A, 1408 Diode; Manufacturer: Bourns; Io_A: 1A; Green_Lifecycle: Not Set; SizeAreaWB_mm2: 12.76; Vr_V: 600V; Green_REACh: Incomplete; TJmax_C: 175°C; Value: 600V; SizeZ_mm: 1.15; SizeX_mm: 3.4; SizeY_mm: 1.9; Vf_V: 1.25V; SizeArea_mm2: 6.46; AEC Qualified: N; AEC Category: Q101; RJC_CperW: 40
D7 = CMP-0085110-1: Diode, Zener, 8.2 V, 500 mW, SOD-123; Manufacturer: Diodes Inc.; SizeAreaWB_mm2: 13.095; RJA_CperW: 425; SizeX_mm: 3.85; Value1: 0.5W; AEC Qualified: N; Power_W: 500mW; SizeY_mm: 1.7; AEC Category: Q101; SizeZ_mm: 1.35; SizeArea_mm2: 6.545
L3 = CMP-03913-61645236-2: POWER INDUCTOR General Purpose Inductor, 1000uH, 10%, 1 Element, SMD, 2424; Inductance Tolerance: 20%; Test Frequency: 100kHz; Saturation Current: 365mA; Self Resonant Frequency: 1.86MHz; Current Rating: 300mA; DC Resistance (DCR): 4.783Ω; Shielding: Shielded
R28 = CMP-0026323-2: RES, 38.3 k, 1%, 0.063 W, AEC-Q200 Grade 0, 0402; Manufacturer: Vishay-Dale; Power_W: 63mW; TempCo: 100 ppm/C; Value_Code: 38k3; Value: 38.3k; EIA_Code: E96; SizeX_mm: 1; SizeY_mm: 0.5; SizeZ_mm: 0.6; Value2: 0.063W; AEC Qualified: Y; VDC_V: 50V; AEC Category: Q200; AEC Grade: 0
R29 = CMP-0026658-1: RES, 10.0 k, 1%, 0.1 W, 0402; Manufacturer: Panasonic; Power_W: 100mW; TempCo: 100 ppm/C; Value_Code: 10k0; U/M: EA; Value: 10.0k; EIA_Code: E96; Res_ohm: 10k; SizeX_mm: 1; SizeY_mm: 0.5; SizeZ_mm: 0.6; Value2: 0.1W; VDC_V: 50V; AEC Category: Q200
TP10 TP11 = CMP-0003825-1: 1mm Test Point, SMT; Manufacturer: Any
U6 = CMP-0074092-2: 700-V Lowest Quiescent Current Off-Line Switcher, D0007A (SOIC-7); Alternate Manufacturer: Texas Instruments; SizeAreaWB_mm2: 55.2; U/M: EA; SizeZ_mm: 1.75; SizeX_mm: 6.0; SizeY_mm: 4.9; SizeArea_mm2: 29.4; CompType: IC; AEC Category: Q200; AEC Qualified: N
U7 = CMP-0034271-1: 150-mA 30-V low-dropout (LDO) linear regulator with 3.2-μA supply current 5-SOT-23 -40 to 125; Manufacturer: Texas Instruments; SizeZ_mm: 1.45mm; AEC Qualified: No; Accuracy Percentage: 4%; Dropout Voltage: 1000mV; Max Supply Voltage: 30V; Min Supply Voltage: 4.3V; Nominal Supply Current: 3.2uA; Number Of Outputs: 1; Output Type: Fixed; Output Voltage: 3.3V; Standoff Height: 0mm; TJmax_C: +125°C

## Sheet TIDA-011030_Mainboard_Hardware.SchDoc: Hardware
size 431 x 279 mm; Date: Not shown in title block; ApprovedBy: Not shown in title block; CheckedBy: Not shown in title block; Author: Not shown in title block; CompanyName: Not shown in title block; Engineer: Not shown in title block; Organization: Not shown in title block; Address1: Not shown in title block; Address2: Not shown in title block; Address3: Not shown in title block; Address4: Not shown in title block; DocumentNumber: 3; Revision: Use project parameter SCH_Rev; SheetNumber: 6; SheetTotal: 6; PageSetup: Record=PageOptions¦CenterHorizontal=True¦CenterVertical=True¦PrintScale=1.00¦XCorrection=1.00¦YCorrection=1.00¦PrintKind=0¦BorderSize=5000000¦LeftOffset=0¦BottomOffset=0¦Orientation=2¦PaperLength=1000¦PaperWidth=1000¦Scale=100¦PaperSource=15¦PrintQuality=600¦MediaType=1¦DitherType=10¦PaperKind=Letter¦PrintScaleMode=1
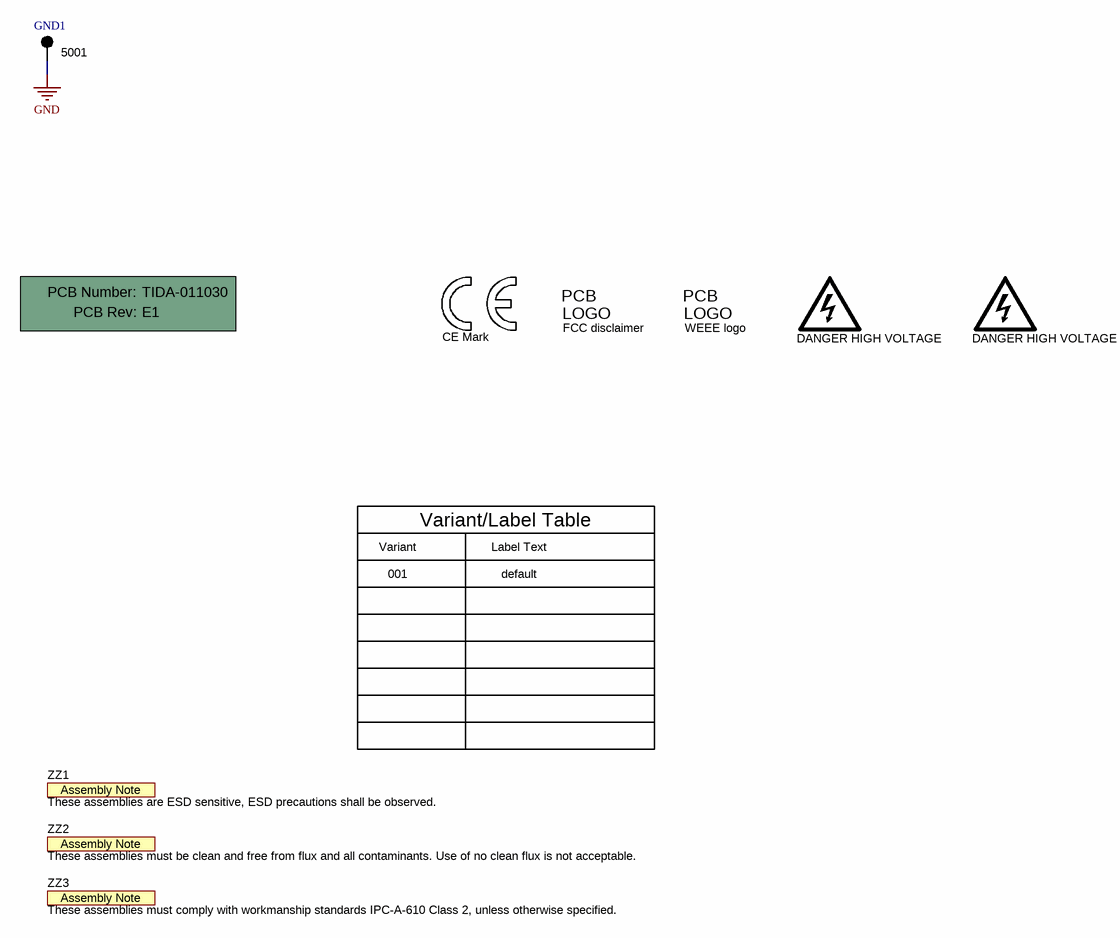
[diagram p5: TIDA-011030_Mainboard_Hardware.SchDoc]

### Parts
(Parts that share a designator on the sheet are numbered #1, #2 ... from top to bottom, then left to right.)
!PCB1  Printed Circuit Board  (value not drawn)  (mechanical)
GND1  5001  [Keystone5001]
LOGO1  DANGER HIGH VOLTAGE  [IEC_HighVoltage_Small]  (no BOM)
Logo2#1  CE Mark  [CE_Mark_5mm]  (no BOM)
LOGO2#2  DANGER HIGH VOLTAGE  [IEC_HighVoltage_Small]  (no BOM)
Logo4  FCC disclaimer  [FCC_disclaimer]  (no BOM)
Logo5  WEEE logo  [WEEE_Minimum]  (no BOM)
ZZ1  These assemblies are ESD sensitive, ESD precautions shall be observed.  [AssemblyNote]  (no BOM)
ZZ2  These assemblies must be clean and free from flux and all contaminants. Use of no clean flux is not acceptable.  [AssemblyNote]  (no BOM)
ZZ3  These assemblies must comply with workmanship standards IPC-A-610 Class 2, unless otherwise specified.  [AssemblyNote]  (no BOM)

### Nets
GND: GND1.1

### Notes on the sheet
- Variant
- Variant/Label Table
- Label Text
- 001
- default

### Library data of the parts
!PCB1 = CMP-0003618-2: Manufacturer: Any; PartNumber: TIDA-011030
GND1 = CMP-0055138-2: Test Point, Miniature, Black, TH; Manufacturer: Keystone Electronics; ContactFinish: Silver; CNHeader: FALSE; Green_Lifecycle: Active; Green_REACh: Passed; CT: TRUE
LOGO1 LOGO2#2 = CMP-0074835-1: IEC 61010-1 High Voltage Warning; SymbolCreator: a0412235; Lib Reference: IEC_HighVoltage
Logo2#1 = CMP-0074844-2: Manufacturer: Texas Instruments; SymbolCreator: a0412235; AEC Category: Q200; CompType: IC
Logo4 = CMP-0074847-1: FCC_disclaimer; Library Reference: Logo
Logo5 = CMP-0074769-4: Manufacturer: Texas Instruments; CompType: IC; AEC Category: Q200
ZZ1 = CMP-0077236-1
ZZ2 = CMP-0077237-1
ZZ3 = CMP-0077238-1

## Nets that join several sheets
3.3V: TIDA-011030_Mainboard_MCU (15 pins), TIDA-011030_Mainboard_Metering (5 pins), TIDA-011030_Mainboard_Power (C34.1 TP11.1 U7.5)
5V: TIDA-011030_Mainboard_MCU (D1.1), TIDA-011030_Mainboard_RelayDRV (C23.1 C24.1 C25.1 U5.1), TIDA-011030_Mainboard_Power (9 pins)
GND: TIDA-011030_Mainboard_MCU (32 pins), TIDA-011030_Mainboard_Metering (11 pins), TIDA-011030_Mainboard_RelayDRV (10 pins), TIDA-011030_Mainboard_Power (10 pins), TIDA-011030_Mainboard_Hardware (GND1.1)
DRV_FB_I: TIDA-011030_Mainboard_MCU (U1.23), TIDA-011030_Mainboard_RelayDRV (C26.1 R27.2 TP9.1 U5.8)
DRV_IN1/EN: TIDA-011030_Mainboard_MCU (U1.3), TIDA-011030_Mainboard_RelayDRV (R26.2 TP7.1 U5.6)
DRV_IN2/PWM: TIDA-011030_Mainboard_MCU (U1.5), TIDA-011030_Mainboard_RelayDRV (R25.2 TP8.1 U5.5)
DRV_OUT1: TIDA-011030_Mainboard_MCU (J2.4), TIDA-011030_Mainboard_RelayDRV (U5.2)
DRV_OUT2: TIDA-011030_Mainboard_MCU (J2.3), TIDA-011030_Mainboard_RelayDRV (U5.3)
I_N: TIDA-011030_Mainboard_MCU (J1.4), TIDA-011030_Mainboard_Metering (FB1.2 TP4.1)
I_P: TIDA-011030_Mainboard_MCU (J1.2), TIDA-011030_Mainboard_Metering (FB2.2 TP6.1)
Line: TIDA-011030_Mainboard_MCU (J2.7 J2.8), TIDA-011030_Mainboard_Metering (R10.2), TIDA-011030_Mainboard_Power (D6.2)
MCU_ADC_I: TIDA-011030_Mainboard_MCU (U1.20), TIDA-011030_Mainboard_Metering (C21.1 R21.2 TP5.1)
MCU_ADC_V: TIDA-011030_Mainboard_MCU (U1.21), TIDA-011030_Mainboard_Metering (C17.1 R13.2 TP3.1)

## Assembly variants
001: not fitted Z2 Z3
